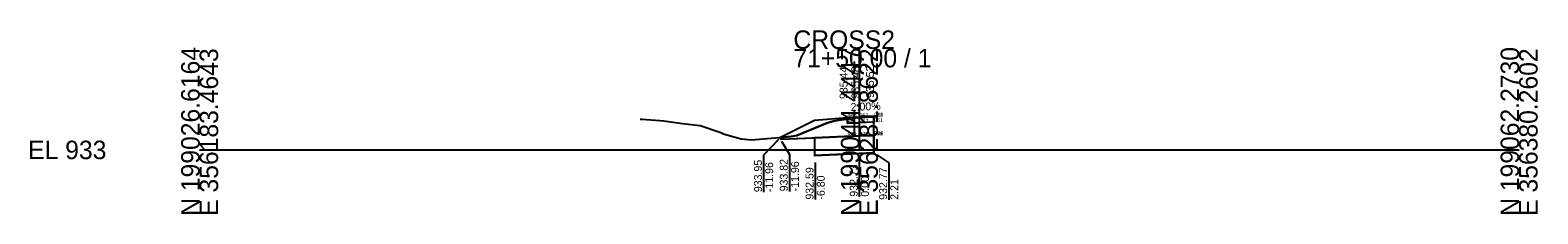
# Model space of a CAD drawing. Extents: x -26 to 203, y -10 to 14021.
# Drawn here: x -25.7 to 202.8, y 12490.3 to 12518.2 of the extents above; entities that cross this region are included whole.
import ezdxf

# ---------------------------------------------------------------- set-up
doc = ezdxf.new("R2010")
doc.units = 0
for name, color, linetype in [('Default', 7, 'Continuous'), ('P_E_XS_Ground', 7, 'Continuous'), ('P_XS', 7, 'Continuous'), ('P_XS_Bold', 7, 'Continuous'), ('P_XS_EAR_CommonGrnd', 7, 'Continuous'), ('P_XS_Lane', 7, 'Continuous'), ('P_XS_Rock', 7, 'Continuous')]:
    doc.layers.add(name, color=color, linetype=linetype)

msp = doc.modelspace()

# ---------------------------------------------------------------- linework, layer by layer
at = {"layer": 'Default'}
for p, q in [((100, 12500), (100, 12515.32)), ((0, 12500), (100, 12500)), ((100, 12500), (200, 12500))]:
    msp.add_line(p, q, dxfattribs=at)
at = {"layer": 'P_E_XS_Ground'}
for p, q in [((66.76, 12504.68), (67.07, 12504.64)), ((67.07, 12504.64), (69.76, 12504.47)), ((69.76, 12504.47), (70.34, 12504.4)), ((70.34, 12504.4), (73.21, 12504.01)), ((73.21, 12504.01), (73.62, 12503.96)), ((73.62, 12503.96), (75.87, 12503.72)), ((75.87, 12503.72), (78.99, 12502.62)), ((90.52, 12502.18), (95.19, 12504.09)), ((95.19, 12504.09), (96.07, 12504.37)), ((96.07, 12504.37), (96.57, 12504.46)), ((96.57, 12504.46), (99.45, 12504.89)), ((99.45, 12504.89), (100, 12504.93)), ((100, 12504.93), (101.76, 12505.05)), ((101.76, 12505.05), (102.2, 12505.11)), ((102.2, 12505.11), (102.25, 12505.11)), ((78.99, 12502.62), (79.42, 12502.42)), ((79.42, 12502.42), (79.89, 12502.29)), ((79.89, 12502.29), (82.07, 12501.68)), ((82.07, 12501.68), (83.68, 12501.53)), ((83.68, 12501.53), (85.41, 12501.69)), ((85.41, 12501.69), (89.65, 12502.03)), ((89.65, 12502.03), (90.52, 12502.18))]:
    msp.add_line(p, q, dxfattribs=at)
at = {"layer": 'P_XS'}
for p, q in [((98.2, 12504.88), (98.2, 12504.05)), ((98.2, 12504.05), (100, 12504.12)), ((102.21, 12504.21), (100, 12504.12)), ((102.21, 12504.21), (102.21, 12505.04)), ((102.21, 12502.21), (102.21, 12504.21)), ((88.04, 12501.64), (100, 12502.12)), ((88.04, 12501.9), (88.04, 12501.64)), ((93.2, 12501.85), (93.2, 12499.18)), ((102.21, 12502.21), (100, 12502.12)), ((102.21, 12502.21), (102.21, 12499.54)), ((102.21, 12499.54), (93.2, 12499.18))]:
    msp.add_line(p, q, dxfattribs=at)
at = {"layer": 'P_XS_EAR_CommonGrnd'}
for points in [[(95.19, 12504.09), (96.07, 12504.37), (96.57, 12504.46), (98.2, 12504.7), (98.2, 12504.88), (93.2, 12504.48), (88.04, 12501.9), (89.65, 12502.03), (90.52, 12502.18)], [(88.04, 12501.9), (88.04, 12501.64), (93.2, 12501.85), (100, 12502.12), (102.21, 12502.21), (102.21, 12504.21), (100, 12504.12), (98.2, 12504.05), (98.2, 12504.7), (96.57, 12504.46), (96.07, 12504.37), (95.19, 12504.09), (90.52, 12502.18), (89.65, 12502.03)], [(100.82, 12504.99), (102.21, 12505.04), (102.21, 12504.21), (100, 12504.12), (98.2, 12504.05), (98.2, 12504.7), (99.45, 12504.89), (100, 12504.93)], [(99.45, 12504.89), (100, 12504.93), (100.82, 12504.99), (100, 12504.95), (98.2, 12504.88), (98.2, 12504.7)], [(100.82, 12504.99), (102.21, 12505.04), (102.21, 12505.11), (101.76, 12505.05)], [(93.2, 12501.85), (93.2, 12499.18), (102.21, 12499.54), (102.21, 12502.21), (100, 12502.12)]]:
    msp.add_lwpolyline(points, close=True, dxfattribs=at)
at = {"layer": 'P_XS_Lane'}
for p, q in [((93.2, 12504.48), (88.04, 12501.9)), ((98.2, 12504.88), (93.2, 12504.48)), ((98.2, 12504.88), (100, 12504.95)), ((100, 12504.95), (102.21, 12505.04)), ((102.21, 12505.04), (102.21, 12505.11))]:
    msp.add_line(p, q, dxfattribs=at)
at = {"layer": 'P_XS_Rock'}
for p, q in [((87.73, 12501.57), (85.48, 12499.21)), ((88.21, 12501.35), (89.39, 12499.31)), ((85.48, 12499.21), (85.48, 12493.6)), ((89.39, 12499.31), (89.39, 12493.72)), ((99.99, 12498.51), (99.99, 12492.91)), ((102.64, 12499.25), (104.45, 12498.03)), ((93.3, 12498.07), (93.3, 12492.47)), ((104.45, 12498.03), (104.45, 12492.44))]:
    msp.add_line(p, q, dxfattribs=at)

# ---------------------------------------------------------------- texts
at = {"layer": 'Default'}
for s, p in [('CROSS2', (90, 12515.32)), ('71+50.00 / 1', (90, 12512.52)), ('EL 933', (-26, 12498.6))]:
    msp.add_text(s, height=2.8, dxfattribs=at).set_placement(p)
for s, p in [('N 199026.6164', (0, 12490)), ('E 356183.4643', (2.8, 12490)), ('N 199044.4447', (100, 12490)), ('E 356281.8622', (102.8, 12490)), ('N 199062.2730', (200, 12490)), ('E 356380.2602', (202.8, 12490))]:
    msp.add_text(s, height=2.8, rotation=90, dxfattribs=at).set_placement(p)
at = {"layer": 'P_XS_Bold'}
for s, p in [('951', (98.2, 12504.88)), ('9', (98.2, 12504.88)), ('900', (98.2, 12504.88)), ('952', (100, 12504.95)), ('952', (100, 12504.95)), ('951', (102.21, 12505.04)), ('9', (102.21, 12505.04)), ('900', (102.21, 12505.04)), ('910', (102.21, 12505.04)), ('961', (98.2, 12504.05)), ('962', (100, 12504.12)), ('962', (100, 12504.12)), ('961', (102.21, 12504.21)), ('971', (98.2, 12502.05)), ('998', (98.2, 12502.05)), ('972', (100, 12502.12)), ('972', (100, 12502.12)), ('971', (102.21, 12502.21)), ('998', (102.21, 12502.21)), ('540', (102.21, 12502.21))]:
    msp.add_text(s, height=0.6, dxfattribs=at).set_placement(p)
at = {"layer": 'P_XS_Rock'}
for s, rotation, p in [('935.44', 90, (98.2, 12507.72)), ('935.48', 90, (100, 12507.79)), ('935.48', 90, (100, 12507.79)), ('935.48', 90, (100, 12507.79)), ('935.48', 90, (100, 12507.79)), ('935.52', 90, (102.21, 12507.88)), ('2.00%', 2.2906, (98.7, 12505.9)), ('933.82', 90, (89.14, 12493.72)), ('933.95', 90, (85.23, 12493.6)), ('-11.96', 90, (86.93, 12493.6)), ('-11.96', 90, (90.84, 12493.72)), ('932.59', 90, (93.05, 12492.47)), ('932.73', 90, (99.74, 12492.91)), ('932.77', 90, (104.2, 12492.44)), ('-6.80', 90, (94.75, 12492.47)), ('0.00', 90, (101.44, 12492.91)), ('2.21', 90, (105.9, 12492.44))]:
    msp.add_text(s, height=1.2, rotation=rotation, dxfattribs=at).set_placement(p)

doc.saveas('drawing.dxf')
